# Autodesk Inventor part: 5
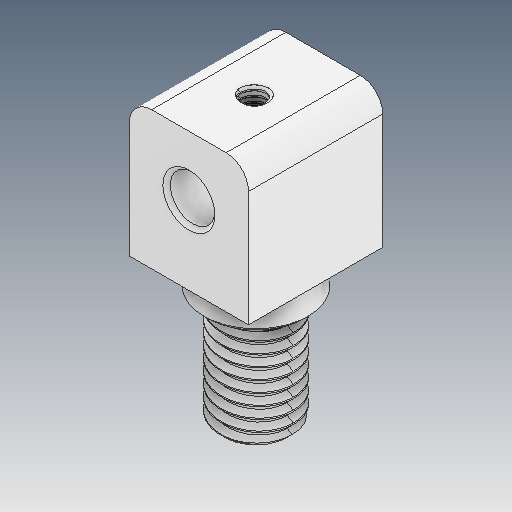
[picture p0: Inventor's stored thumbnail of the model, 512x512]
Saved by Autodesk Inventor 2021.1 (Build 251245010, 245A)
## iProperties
Created: 2021-06
Part Number: 5
Material: Ogólny
Document SubType Name: Modeling
Designer: user
Density: 1 g/cm^3
Appearance: Domyślna
Author: user
Revision Number: ÈÎºÎ
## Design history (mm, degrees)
feature "ÊäÈë1"
node "Bryła1"
